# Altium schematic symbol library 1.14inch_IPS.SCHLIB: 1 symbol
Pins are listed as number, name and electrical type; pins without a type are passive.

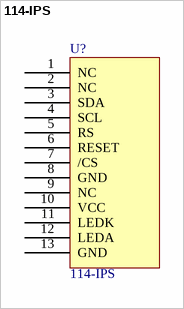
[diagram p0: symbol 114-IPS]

## 114-IPS
designator U?
1.14 TFT IPS
footprint 144-IPS (1.44 TFT IPS)
pins: 1 NC, 2 NC, 3 SDA, 4 SCL, 5 RS, 6 RESET, 7 /CS, 8 GND, 9 NC, 10 VCC, 11 LEDK, 12 LEDA, 13 GND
